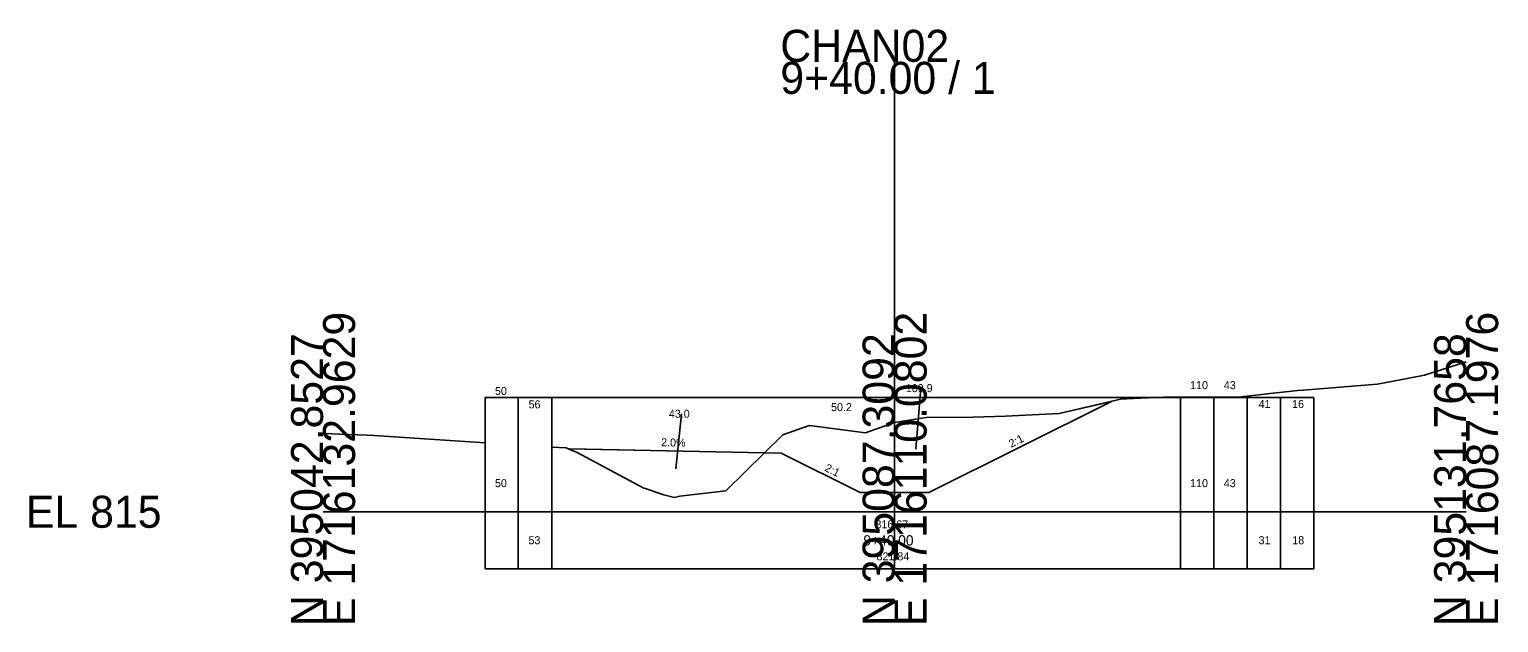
# Model space of a CAD drawing. Extents: x -26 to 103, y -10 to 16052.
# Drawn here: x -25.7 to 102.8, y 3490.3 to 3542.2 of the extents above; entities that cross this region are included whole.
import ezdxf

# ---------------------------------------------------------------- set-up
doc = ezdxf.new("R2010")
doc.units = 0
for name, color, linetype in [('GK_Cells', 7, 'Continuous'), ('SH_Text', 7, 'Continuous'), ('XS_P_Annotation', 7, 'Continuous'), ('XS_P_Boundary', 7, 'Continuous'), ('XS_P_Earthwork_Shapes', 7, 'Continuous'), ('XS_P_Finished_Grade', 7, 'Continuous'), ('XS_X_Ground_Line', 7, 'Continuous')]:
    doc.layers.add(name, color=color, linetype=linetype)

msp = doc.modelspace()

# ---------------------------------------------------------------- linework, layer by layer
at = {"layer": 'GK_Cells'}
for p, q in [((50, 3500), (50, 3539.34)), ((0, 3500), (50, 3500)), ((50, 3500), (100, 3500))]:
    msp.add_line(p, q, dxfattribs=at)
at = {"layer": 'XS_P_Boundary'}
for p, q in [((17.08, 3495.01), (17.08, 3509.99)), ((20, 3495.01), (20, 3509.99)), ((50, 3495.01), (50, 3509.99)), ((75, 3495.01), (75, 3509.99)), ((77.92, 3495.01), (77.92, 3509.99)), ((80.83, 3495.01), (80.83, 3509.99)), ((83.75, 3495.01), (83.75, 3509.99)), ((15.63, 3502.5), (15.63, 3502.5)), ((76.46, 3502.5), (76.46, 3502.5)), ((79.38, 3502.5), (79.38, 3502.5)), ((18.54, 3497.51), (18.54, 3497.51)), ((82.29, 3497.51), (82.29, 3497.51)), ((85.21, 3497.51), (85.21, 3497.51))]:
    msp.add_line(p, q, dxfattribs=at)
msp.add_lwpolyline([(14.17, 3495.01), (14.17, 3509.99), (86.67, 3509.99), (86.67, 3495.01)], close=True, dxfattribs=at)
at = {"layer": 'XS_P_Earthwork_Shapes'}
for p, q in [((51.86, 3505.47), (52.28, 3510.81)), ((53, 3501.67), (68.96, 3509.65)), ((68.96, 3509.65), (64.4, 3508.6)), ((30.85, 3503.74), (31.37, 3508.57)), ((38.62, 3505.16), (21.6, 3505.5)), ((38.62, 3505.16), (40.08, 3505.13)), ((40.08, 3505.13), (47, 3501.67)), ((47, 3501.67), (53, 3501.67))]:
    msp.add_line(p, q, dxfattribs=at)
for points in [[(21.44, 3505.5), (40.08, 3505.13), (47, 3501.67), (53, 3501.67), (68.96, 3509.65)], [(64.4, 3508.6), (59.7, 3508.35), (56.87, 3508.27), (52.75, 3508.24), (50, 3507.81), (47.45, 3506.9), (42.55, 3507.54), (42.03, 3507.36), (40.23, 3506.74), (38.62, 3505.16)], [(21.6, 3505.5), (21.6, 3505.43)], [(21.6, 3505.43), (22.22, 3505.19), (27.99, 3502.1), (29.81, 3501.47), (30.75, 3501.25), (31.22, 3501.37), (35.23, 3501.82), (38.62, 3505.16)]]:
    msp.add_lwpolyline(points, dxfattribs=at)
at = {"layer": 'XS_P_Finished_Grade'}
for p, q in [((68.96, 3509.65), (53, 3501.67)), ((40.08, 3505.13), (21.44, 3505.5)), ((40.08, 3505.13), (47, 3501.67)), ((47, 3501.67), (53, 3501.67))]:
    msp.add_line(p, q, dxfattribs=at)
at = {"layer": 'XS_X_Ground_Line'}
for points in [[(20, 3505.66), (21.28, 3505.58), (21.6, 3505.43), (22.22, 3505.19), (27.99, 3502.1), (29.81, 3501.47), (30.75, 3501.25), (31.22, 3501.37), (35.23, 3501.82), (40.23, 3506.74), (42.03, 3507.36), (42.55, 3507.54), (47.45, 3506.9), (50, 3507.81), (52.75, 3508.24), (56.87, 3508.27), (59.7, 3508.35), (64.4, 3508.6), (69.77, 3509.84), (70.91, 3509.9), (73.53, 3510.03), (80.08, 3510.02), (83.13, 3510.38), (84.76, 3510.54), (85.24, 3510.59), (85.74, 3510.64), (92.22, 3511.16), (92.87, 3511.28), (96.37, 3511.93), (100, 3513.11)], [(0, 3506.84), (0.78, 3506.81), (1.44, 3506.78), (3.85, 3506.69), (4.47, 3506.66), (14.17, 3506.03)]]:
    msp.add_lwpolyline(points, dxfattribs=at)

# ---------------------------------------------------------------- texts
at = {"layer": 'GK_Cells'}
for s, p in [('CHAN02', (40, 3539.34)), ('9+40.00 / 1', (40, 3536.54)), ('EL 815', (-26, 3498.6))]:
    msp.add_text(s, height=2.8, dxfattribs=at).set_placement(p)
for s, p in [('E 1716132.9629', (2.8, 3490)), ('E 1716110.0802', (52.8, 3490)), ('E 1716087.1976', (102.8, 3490)), ('N 395042.8527', (0, 3490)), ('N 395087.3092', (50, 3490)), ('N 395131.7658', (100, 3490))]:
    msp.add_text(s, height=2.8, rotation=90, dxfattribs=at).set_placement(p)
at = {"layer": 'SH_Text'}
for s, p in [('50', (15.04, 3510.21)), ('110', (75.85, 3510.72)), ('43', (78.8, 3510.72)), ('56', (17.98, 3509.04)), ('41', (81.84, 3509.07)), ('16', (84.77, 3509.07)), ('50', (15.04, 3502.15)), ('110', (75.85, 3502.15)), ('43', (78.8, 3502.15)), ('53', (17.97, 3497.16)), ('31', (81.84, 3497.16)), ('18', (84.79, 3497.16))]:
    msp.add_text(s, height=0.7, dxfattribs=at).set_placement(p)
at = {"layer": 'XS_P_Annotation'}
for s, rotation, p in [('2.0%', 358.8542, (29.57, 3505.73)), ('2:1', 26.5651, (60.21, 3505.59)), ('2:1', 333.4349, (43.82, 3503.61))]:
    msp.add_text(s, height=0.7, rotation=rotation, dxfattribs=at).set_placement(p)
for s, height, p in [('816.67', 0.7, (48.32, 3498.55)), ('9+40.00', 0.9, (47.27, 3497.05)), ('821.84', 0.7, (48.42, 3495.75))]:
    msp.add_text(s, height=height, dxfattribs=at).set_placement(p)
at = {"layer": 'XS_P_Earthwork_Shapes'}
for s, p in [('109.9', (50.98, 3510.46)), ('50.2', (44.44, 3508.8)), ('43.0', (30.25, 3508.22))]:
    msp.add_text(s, height=0.7, dxfattribs=at).set_placement(p)

doc.saveas('drawing.dxf')
